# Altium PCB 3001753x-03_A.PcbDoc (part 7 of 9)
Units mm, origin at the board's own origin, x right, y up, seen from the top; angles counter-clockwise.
Board outline 210 x 130 mm, 8 copper layers (1-TOP, 2-GND, 3-INTOP, 4-PWR, 5-PWR, 6-INBOT, 7-GND, 8-BOTTOM), stack 1.646 mm thick; 676 components, 623 nets, 2861 pads, 2382 vias.
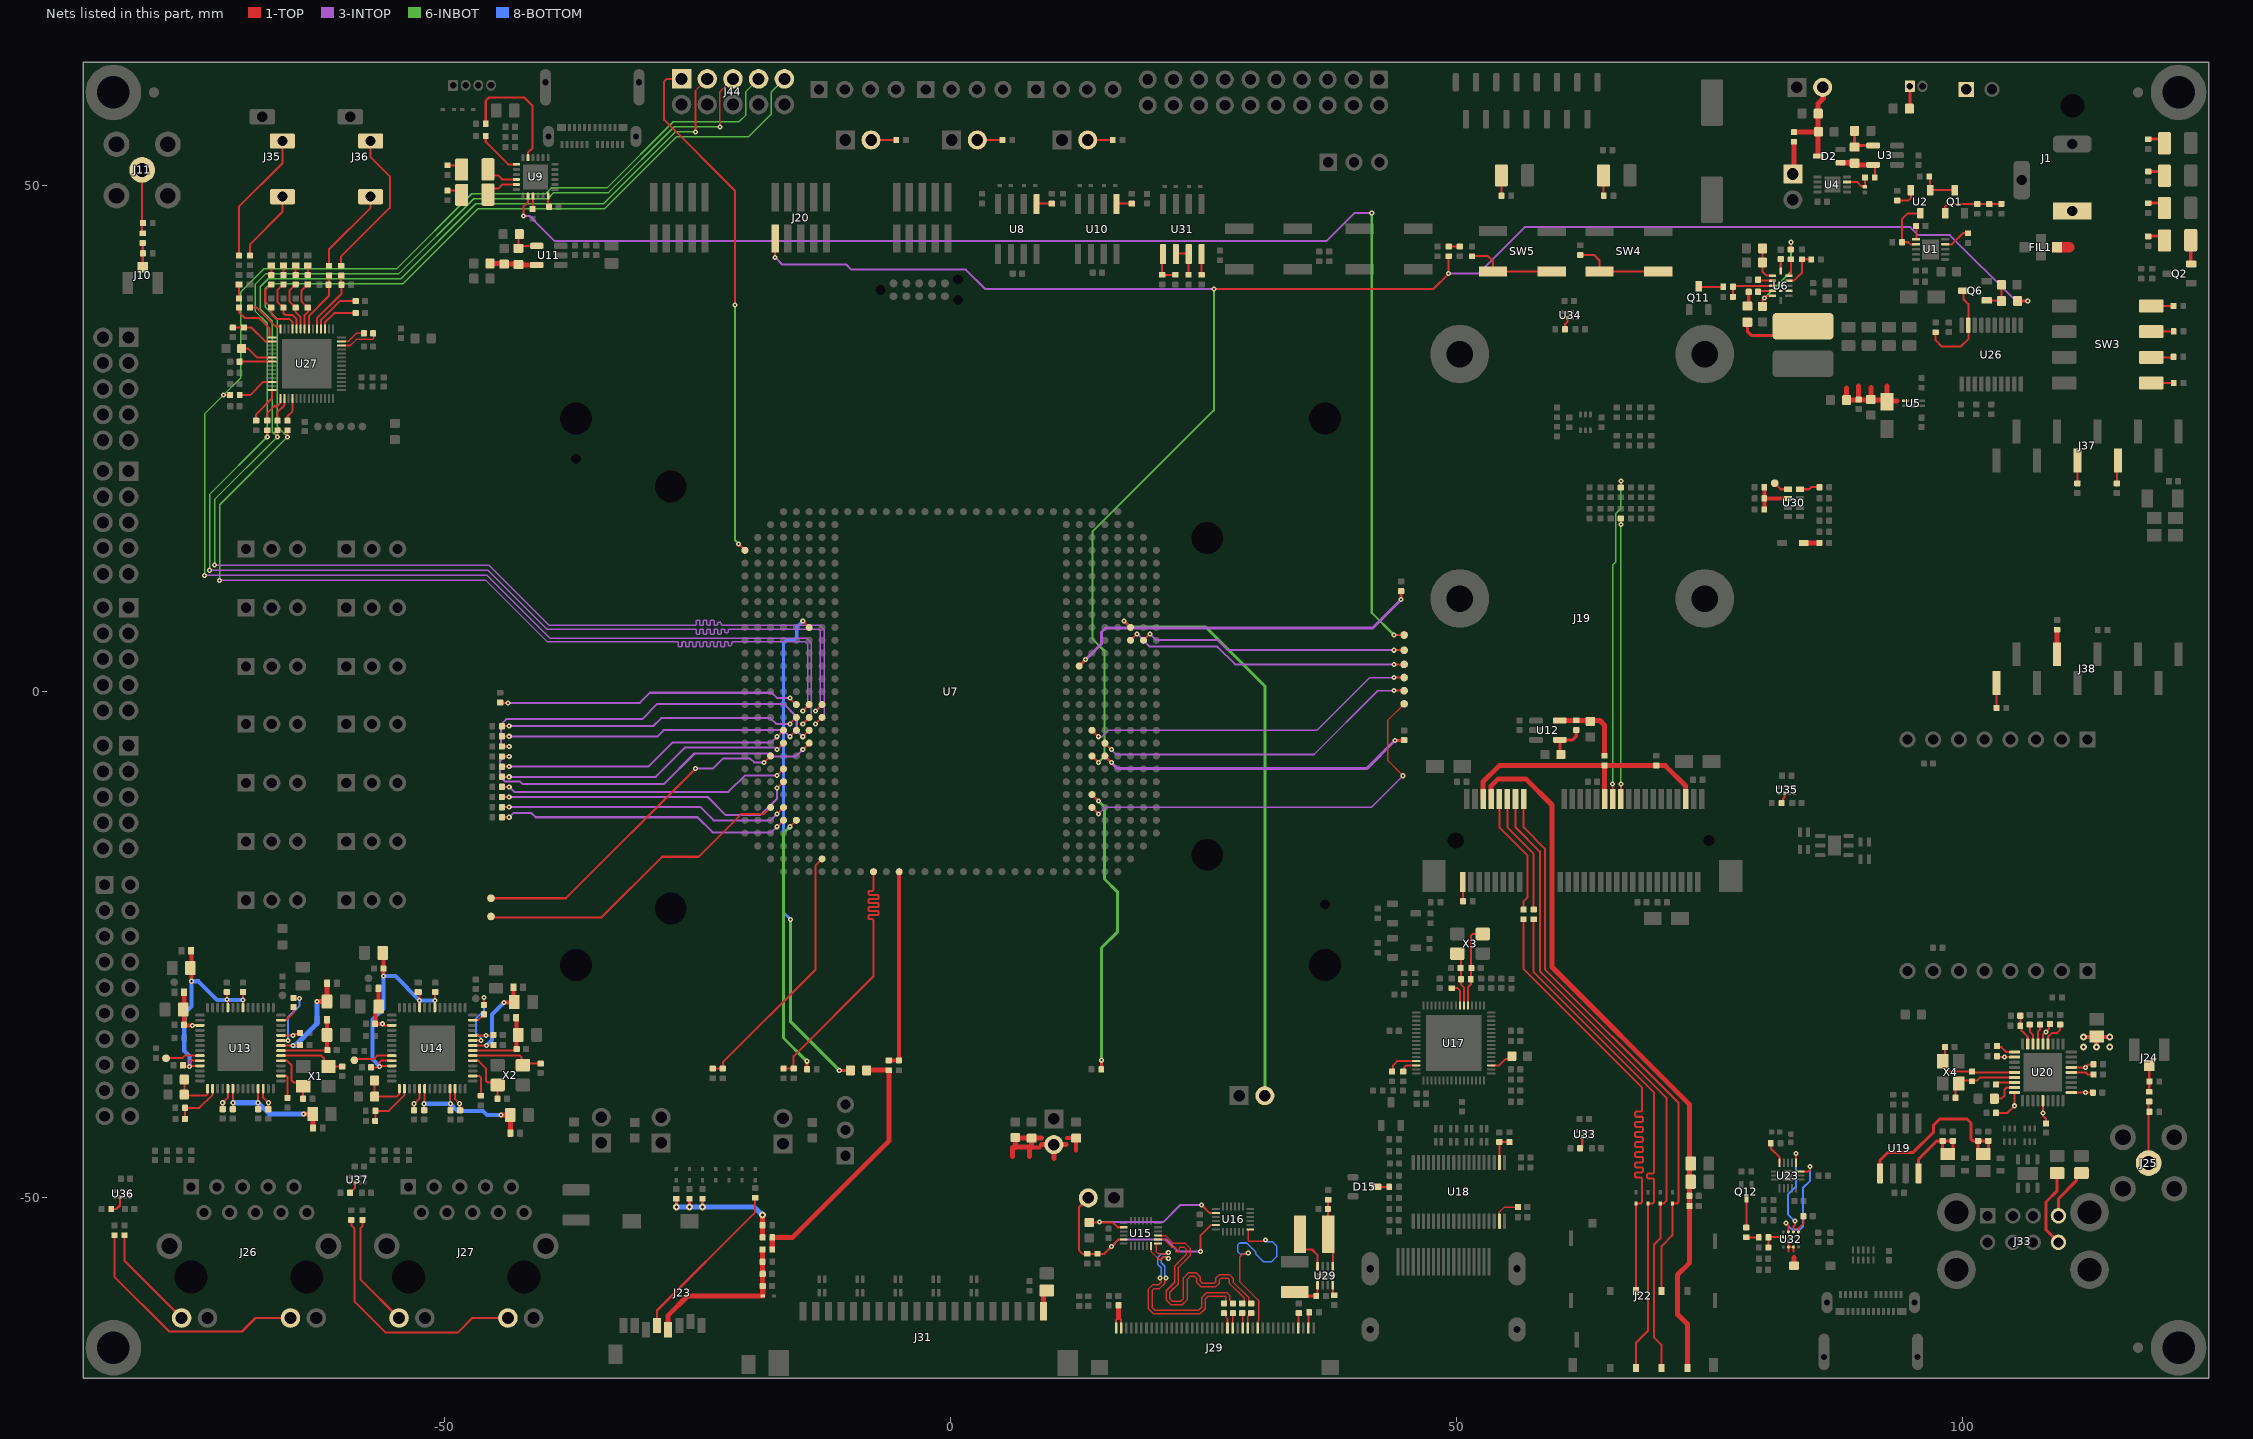
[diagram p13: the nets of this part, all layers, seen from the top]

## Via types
v1: diameter 0.5, hole 0.2, 1-TOP to 8-BOTTOM, 1547 vias
v2: diameter 0.68, hole 0.3, 1-TOP to 8-BOTTOM, 835 vias

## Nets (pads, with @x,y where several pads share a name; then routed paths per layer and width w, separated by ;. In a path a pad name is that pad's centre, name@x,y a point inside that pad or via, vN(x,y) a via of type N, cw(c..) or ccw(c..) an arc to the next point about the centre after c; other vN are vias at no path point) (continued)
MIPI_EXT_DATA1_P: J29.29 U16.19 | length 21
  1-TOP w0.15: v1(29.4,-55.423) 29.4,-55.446 29.3,-55.546 28.854,-55.546 28.546,-55.854 28.546,-58.246 30.423,-60.123 30.423,-61.823 30.423,-62.09 30.35,-62.163 J29.29@30.35,-62.85 ; U16.19@29.4,-53.1 29.4,-54.2 29.5,-54.3 30.977,-54.3 v1(31.1,-54.177)
  8-BOTTOM w0.15: v1(29.4,-55.423) 29.277,-55.546 28.596,-55.546 28.354,-55.304 28.354,-54.647 28.547,-54.454 29.254,-54.454 30.146,-55.346 30.146,-55.546 30.9,-56.3 31.7,-56.3 32.204,-55.796 32.204,-54.729 31.809,-54.334 31.257,-54.334 v1(31.1,-54.177)
MIPI_EXT_DATA2_N: R220.2 U15.21 | length 22.7
  1-TOP w0.15: U15.21@20.495,-53.7 20.518,-53.723 21.224,-53.723 22.001,-54.5 23.2,-54.5 23.65,-54.95 23.65,-55.719 22.5,-56.869 22.5,-58.476 21.654,-59.322 21.654,-59.929 21.925,-60.2 22.725,-60.2 23,-59.925 23,-57.9 23.5,-57.4 24.25,-57.4 24.679,-57.829 24.679,-58.228 24.897,-58.446 26.028,-58.446 26.2,-58.274 26.2,-57.925 26.55,-57.575 27.543,-57.575 27.897,-57.929 27.897,-58.296 29.464,-59.863 29.464,-60.384 R220.2@29.5,-60.42
MIPI_EXT_DATA2_P: R221.2 U15.20 | length 22.6
  1-TOP w0.15: U15.20@20.495,-54.1 20.518,-54.077 21.077,-54.077 21.854,-54.854 22.146,-54.854 22.234,-54.942 22.234,-55.281 22.286,-55.333 22.531,-55.333 22.584,-55.281 22.584,-54.942 22.672,-54.854 23.053,-54.854 23.296,-55.097 23.296,-55.572 22.146,-56.722 22.146,-58.329 21.3,-59.175 21.3,-60.076 21.778,-60.554 22.872,-60.554 23.354,-60.072 23.354,-58.047 23.647,-57.754 24.103,-57.754 24.325,-57.976 24.325,-58.375 24.75,-58.8 26.175,-58.8 26.554,-58.421 26.554,-58.071 26.696,-57.929 27.396,-57.929 27.543,-58.075 27.543,-58.443 29,-59.9 R221.2@29,-60.2
MIPI_EXT_DATA3_N: R222.2 U15.18 | length 19.7
  1-TOP w0.15: U15.18@19.8,-54.745 19.8,-55.3 20.35,-55.85 20.449,-55.85 20.537,-55.938 20.537,-56.051 20.59,-56.103 20.835,-56.103 20.887,-56.051 20.887,-55.938 20.975,-55.85 21.373,-55.85 v1(21.5,-55.977) ; v1(21.277,-57.9) 21.154,-58.023 21.154,-58.447 20.647,-58.954 20.097,-58.954 19.9,-59.151 19.9,-59.649 19.9,-60.175 19.9,-60.799 20.201,-61.1 24.499,-61.1 24.8,-60.799 24.8,-59.85 25.304,-59.346 27.27,-59.346 27.554,-59.63 27.554,-60.074 R222.2@27.9,-60.42
  8-BOTTOM w0.15: v1(21.277,-57.9) 21.154,-57.777 21.154,-56.753 20.8,-56.399 20.8,-56.054 21,-55.854 21.377,-55.854 v1(21.5,-55.977)
MIPI_EXT_DATA3_P: R223.2 U15.19 | length 19.4
  1-TOP w0.15: U15.19@20.3,-54.5 20.3,-55.3 20.5,-55.5 21.377,-55.5 v1(21.5,-55.377) ; v1(20.677,-57.9) 20.8,-58.023 20.8,-58.3 20.5,-58.6 19.95,-58.6 19.546,-59.004 19.546,-60.946 20.054,-61.454 24.646,-61.454 25.154,-60.946 25.154,-59.997 25.451,-59.7 27.123,-59.7 27.2,-59.777 27.2,-60.32 R223.2@27.1,-60.42
  8-BOTTOM w0.15: v1(20.677,-57.9) 20.8,-57.777 20.8,-56.9 20.446,-56.546 20.446,-55.907 20.853,-55.5 21.377,-55.5 v1(21.5,-55.377)
MIPI_SWITCH_OE: R116.2 U15.8 U16.8 | length 16.1
  1-TOP w0.2: R116.2@13.7,-52.43 16.03,-52.43 16.5,-52.9 U15.8@17.105,-52.9 ; v1(24.8,-50.7) 25.6,-51.5 U16.8@26.205,-51.5
  3-INTOP w0.2: v1(14.7,-52.4) 21,-52.4 22.7,-50.7 v1(24.8,-50.7)
MIPI_SWITCH_SEL: J28.2 R115.2 R117.1 U15.11 U16.11 | length 23.8
  1-TOP w0.2: J28.2@13.6,-50 12.7,-50.9 12.7,-55.2 13.02,-55.52 R117.1@13.5,-55.52 R115.2@14.5,-55.52 15.18,-55.52 v1(15.9,-54.8) 16.6,-54.1 U15.11@17.105,-54.1 ; v1(24.7,-55.3) 24.7,-53.7 25.7,-52.7 U16.11@26.205,-52.7
  3-INTOP w0.2: v1(15.9,-54.8) 16.6,-54.1 21.3,-54.1 22.5,-55.3 v1(24.7,-55.3)
MUX_3V3_1V8: R38.1 R39.1 R84.2 R85.2 | length 25.8
  1-TOP w0.5: R85.2@-17.62,-55.1 R84.2@-17.62,-53.9 -15.6,-53.9 -6.1,-44.4 R39.1@-6.1,-37.4 ; R38.1@-8.28,-37.38 R39.1@-6.1,-37.38
NetC5_2: C5.2 U1.6 | length 1.3
  1-TOP w0.2: U1.6@95.4,44.7 95.4,45.76 C5.2@95.54,45.9
NetC6_1: C6.1 Q1.G R13.2 R14.1 | length 6.3
  1-TOP w0.2: Q1.G@98.25,47.25 98.25,47.95 98.48,48.18 R14.1@101.4,48.18 R13.2@103.8,48.18
NetC7_2: C7.2 D2.3 J3.2 R16.1 R18.2 | length 8.9
  1-TOP w0.5: R18.2@83.3,55.28 C7.2@85.71,55.28 ; D2.3@85.7,52.9 C7.2@85.7,55.27 ; R16.1@85.7,56.6 85.7,55.33 C7.2@85.73,55.3 ; R16.1@85.7,57.1 85.7,58.1 86.2,58.6 86.2,59.64 J3.2@86.14,59.7
NetC11_1: C11.1 U6.10 | length 1.4
  1-TOP w0.2: C11.1@79.76,39.6 U6.10@81.2,39.6
NetC11_2: C11.2 R23.1 | length 1.6
  1-TOP w0.3: R23.1@78.7,38.1 78.84,38.24 C11.2@78.84,39.6
NetC16_1: C16.1 C21.2 C22.2 R24.1 U5.1 | length 9.9
  1-TOP w0.2: C16.1@92.35,28.8 C16.1@92.5,28.65
  1-TOP w0.5: 88.5,30 R24.1@88.5,28.8 89.7,28.8 90.9,28.8 C16.1@92.35,28.8 ; C22.2@89.7,29 89.7,30.2 ; C21.2@90.9,28.87 90.9,30.07 ; C16.1@92.425,28.725 93.5,28.725 ; C16.1@92.5,29 92.5,30.2
NetC23_1: C23.1 U6.8 | length 1.5
  1-TOP w0.2: C23.1@79.76,40.7 79.86,40.6 U6.8@81.2,40.6
NetC24_2: C24.2 R30.1 U6.11 | length 9.1
  1-TOP w0.2: C24.2@80.2,38.07 80.2,38.7 v1(80.4,38.9) 80.6,39.1 U6.11@81.2,39.1 ; R30.1@83,43.68 v1(83,44.4)
  6-INBOT w0.2: v1(80.4,38.9) 83,41.5 v1(83,44.4)
NetC25_2: C25.2 U6.6 | length 1.2
  1-TOP w0.2: U6.6@82,41.55 C25.2@82,42.74
NetC31_1: C31.1 U9.12 | length 1.1
  1-TOP w0.2: U9.12@-39.75,48.95 -39.75,47.99 C31.1@-39.66,47.9
NetC33_2: C33.2 R74.1 R76.2 U11.5 | length 4.7
  1-TOP w0.2: C33.2@-44.17,42.3 C33.2@-44.1,42.23 ; R76.2@-42.73,42.23 R76.2@-42.7,42.2
  1-TOP w0.5: R74.1@-45.5,42.3 C33.2@-44.17,42.3 ; C33.2@-44.1,42.23 R76.2@-42.73,42.23 ; R76.2@-42.7,42.15 U11.5@-40.88,42.15
NetC38_2: C38.2 R81.1 R82.2 U12.5 | length 7.6
  1-TOP w0.5: U12.5@60.18,-2.85 61.8,-2.85 63.2,-2.85 64.15,-2.85 64.6,-3.3 R81.1@64.6,-6.32
NetC48_2: C48.2 C49.2 D1.1 J23.4 R85.1 R88.1 | length 16.2
  1-TOP w0.5: J23.4@-27.9,-63.025 -27.9,-61.6 -26,-59.7 -18.56,-59.7 C48.2@-18.56,-58.7 ; C48.2@-18.58,-58.7 -18.58,-57.5 R88.1@-18.58,-56.3 R85.1@-18.58,-55.1
NetC58_2: C58.2 C59.2 L2.1 U13.36 | length 10.3
  1-TOP w0.2: U13.36@-66.15,-34.95 v1(-64.95,-34.95) C58.2@-64.41,-34.95 ; C58.2@-64.5,-34.95 C58.2@-64.41,-34.95 ; C58.2@-64.5,-34.9 -64.36,-34.9 C58.2@-64.41,-34.95
  1-TOP w0.5: v1(-62.6,-30.6) C59.2@-61.6,-30.6 -61.58,-30.58 L2.1@-61.58,-28.8
  8-BOTTOM w0.5: v1(-64.95,-34.95) -64.75,-34.95 -62.6,-32.8 v1(-62.6,-30.6)
NetC60_2: C60.2 C61.2 C62.2 L3.1 U13.20 U13.25 | length 14
  1-TOP w0.2: C61.2@-70.9,-41.34 v1(-70.9,-40.6) U13.20@-70.9,-39.2 ; C60.2@-68.4,-41.34 v1(-68.4,-40.6) U13.25@-68.4,-39.2
  1-TOP w0.5: v1(-63.9,-41.7) C62.2@-63,-41.7 -62.98,-41.72 L3.1@-62.98,-43.1
  8-BOTTOM w0.5: v1(-70.9,-40.6) v1(-68.4,-40.6) -67.3,-41.7 v1(-63.9,-41.7)
NetC63_2: C63.2 C64.2 C65.2 C66.2 L4.1 U13.10 U13.11 U13.49 U13.52 | length 24.3
  1-TOP w0.2: C63.2@-75.84,-36.9 C63.2@-75.74,-36.8 ; C63.2@-75.8,-37 v1(-75.2,-37) ; L4.1@-75.02,-25.6 L4.1@-75,-25.62 ; U13.11@-74.15,-36.95 -75.15,-36.95 v1(-75.2,-37) ; U13.10@-74.15,-36.45 -75.05,-36.45 -75.2,-36.6 v1(-75.2,-37) ; C65.2@-71.5,-29.66 v1(-71.5,-30.4) -71.4,-30.4 U13.52@-71.4,-31.2 ; U13.49@-69.9,-31.2 v1(-69.9,-30.43) C64.2@-69.9,-29.66
  1-TOP w0.4: v1(-75,-28.6) L4.1@-75,-25.62
  8-BOTTOM w0.4: v1(-75.2,-37) -75.2,-36 -75.7,-35.5 -75.7,-31.8 -75,-31.1 v1(-75,-28.6) -74.3,-28.6 -72.47,-30.43 -71.53,-30.43 v1(-71.5,-30.4) -71.47,-30.43 v1(-69.9,-30.43)
NetC67_1: C67.1 R103.1 U13.16 | length 4.9
  1-TOP w0.2: C67.1@-75.64,-42.2 -75.64,-41.12 R103.1@-75.62,-41.1 ; R103.1@-75.6,-41.1 -74.2,-41.1 -72.9,-39.8 U13.16@-72.9,-39.2
NetC68_2: C68.2 U13.34 X1.1 | length 6.3
  1-TOP w0.2: U13.34@-66.15,-35.95 -62.15,-35.95 -61.9,-36.2 X1.1@-61.9,-36.8 ; X1.1@-61.45,-37.025 -61.435,-37.04 C68.2@-60.1,-37.04
NetC69_2: C69.2 C70.2 L5.1 U13.35 | length 7.1
  1-TOP w0.2: U13.35@-66.15,-35.45 C69.2@-61.76,-35.45 ; C69.2@-61.6,-35.36 C69.2@-61.56,-35.4
  1-TOP w0.4: C69.2@-61.6,-35.36 C70.2@-61.6,-33.9 ; C70.2@-61.58,-33.9 L5.1@-61.58,-32.72
NetC71_2: C71.2 U13.33 X1.3 | length 4.6
  1-TOP w0.2: U13.33@-66.15,-36.45 -65.55,-36.45 -65.1,-36.9 -65.1,-38.4 -64.9,-38.6 X1.3@-64.5,-38.6 ; C71.2@-63.96,-40.2 -63.96,-38.985 X1.3@-63.95,-38.975
NetC72_2: C72.2 C73.2 C74.2 C75.2 C76.2 L6.1 U13.3 U13.19 U13.26 U13.38 | length 11.2
  1-TOP w0.2: v1(-74.9,-32.95) U13.3@-74.15,-32.95 ; C73.2@-71.9,-41.34 v1(-71.9,-40.6) -71.4,-40.1 U13.19@-71.4,-39.2 ; U13.26@-67.9,-39.2 -67.9,-40.1 v1(-67.4,-40.6) C74.2@-67.4,-41.34 ; U13.38@-66.15,-33.95 v1(-64.95,-33.95) -64.8,-33.8 C75.2@-64.5,-33.8
  1-TOP w0.4: L6.1@-75.82,-29.7 -75.7,-29.82 -75.7,-32.9 -75.65,-32.95 v1(-74.9,-32.95)
NetC80_1: C80.1 U13.37 | length 6
  1-TOP w0.2: U13.37@-66.15,-34.45 v1(-65.45,-34.45) ; C80.1@-64.9,-30.24 -64.84,-30.3 v1(-64.3,-30.3)
  8-BOTTOM w0.2: v1(-65.45,-34.45) -65.45,-32.15 -64.3,-31 v1(-64.3,-30.3)
NetC80_2: C80.2 U13.41 | length 2.1
  1-TOP w0.2: U13.41@-66.15,-32.45 -65.65,-32.45 -64.9,-31.7 C80.2@-64.9,-31.16
NetC85_2: C85.2 C86.2 L7.1 U14.36 | length 9.4
  1-TOP w0.2: U14.36@-47.2,-34.95 v1(-45.85,-34.95) -45.21,-34.95 C85.2@-45.16,-34.9
  1-TOP w0.4: v1(-44.1,-30.7) C86.2@-43.145,-30.7 ; L7.1@-43.2,-29.27 -43.2,-30.54 C86.2@-43.09,-30.65
  8-BOTTOM w0.4: v1(-45.85,-34.95) -45.3,-34.4 -45.3,-31.9 v1(-44.1,-30.7)
NetC87_2: C87.2 C88.2 C89.2 L8.1 U14.20 U14.25 | length 15.2
  1-TOP w0.2: C88.2@-51.95,-41.29 C88.2@-52,-41.34 v1(-52,-40.7) -51.95,-40.65 U14.20@-51.95,-39.2 ; U14.25@-49.45,-39.2 -49.45,-40.65 v1(-49.4,-40.7) C87.2@-49.4,-41.34
  1-TOP w0.4: C89.2@-43.5,-41.8 C89.2@-43.48,-41.82
  1-TOP w0.5: v1(-44.4,-41.8) C89.2@-43.5,-41.8 ; L8.1@-43.48,-43.6 C89.2@-43.48,-41.82
  8-BOTTOM w0.4: v1(-52,-40.7) v1(-49.4,-40.7) -48.7,-41.4 -46.2,-41.4 -45.8,-41.8 v1(-44.4,-41.8)
NetC90_2: C90.2 C91.2 C92.2 C93.2 L9.1 U14.10 U14.11 U14.49 U14.52 | length 25
  1-TOP w0.2: C90.2@-57.24,-37.1 -56.4,-37.1 v1(-56.4,-37) ; C93.2@-56.1,-25.8 C93.2@-56.03,-25.87 ; U14.11@-55.2,-36.95 -56.35,-36.95 v1(-56.4,-37) ; U14.10@-55.2,-36.45 -56.25,-36.45 -56.4,-36.6 v1(-56.4,-37) ; L9.1@-52.6,-29.68 -52.45,-29.83 v1(-52.45,-30.5) U14.52@-52.45,-31.2 ; U14.49@-50.95,-31.2 v1(-50.95,-30.5) -50.95,-29.71 C92.2@-50.9,-29.66
  1-TOP w0.4: v1(-56.03,-28.1) C91.2@-56.03,-27.35 C93.2@-56.03,-25.87
  8-BOTTOM w0.4: v1(-56.4,-37) -57.1,-36.3 -57.1,-32.4 -56.03,-31.33 v1(-56.03,-28.1) -54.85,-28.1 v1(-52.45,-30.5) v1(-50.95,-30.5)
NetC94_1: C94.1 R112.1 U14.16 | length 5.2
  1-TOP w0.2: C94.1@-56.82,-42.5 C94.1@-56.82,-42.4 ; C94.1@-56.82,-42.32 R112.1@-56.82,-41.4 -55.5,-41.4 -53.95,-39.85 U14.16@-53.95,-39.2
NetC95_2: C95.2 U14.34 X2.1 | length 7.2
  1-TOP w0.2: U14.34@-47.2,-35.95 -42.55,-35.95 -42.4,-36.1 X2.1@-42.4,-36.6 ; X2.1@-42.25,-36.9 -42.09,-36.74 C95.2@-40.5,-36.74
NetC96_2: C96.2 C97.2 L10.1 U14.35 | length 7.8
  1-TOP w0.2: U14.35@-47.2,-35.45 C96.2@-42.9,-35.45 ; C97.2@-43,-33.6 -42.86,-33.74 C97.2@-42.7,-33.9
  1-TOP w0.4: C96.2@-42.86,-35.3 -42.86,-34.26 -42.86,-33.74 L10.1@-42.86,-32.2
NetC98_2: C98.2 U14.33 X2.3 | length 5.2
  1-TOP w0.2: U14.33@-47.2,-36.45 -46.65,-36.45 -45.9,-37.2 -45.9,-38.4 -45.7,-38.6 X2.3@-45.2,-38.6 ; X2.3@-44.9,-38.4 X2.3@-44.75,-38.55 ; C98.2@-44.76,-40.2 -44.76,-38.86 X2.3@-44.75,-38.85
NetC99_2: C99.2 C100.2 C101.2 C102.2 C103.2 L11.1 U14.3 U14.19 U14.26 U14.38 | length 12.1
  1-TOP w0.2: C103.2@-56.64,-31.24 C103.2@-56.5,-31.1 C103.2@-56.52,-31.08 ; v1(-56.1,-32.8) -55.95,-32.95 U14.3@-55.2,-32.95 ; C100.2@-53,-41.34 v1(-53,-40.7) -52.45,-40.15 U14.19@-52.45,-39.2 ; U14.26@-48.95,-39.2 -48.95,-40.25 v1(-48.5,-40.7) -48.5,-41.29 C101.2@-48.45,-41.34 ; U14.38@-47.2,-33.95 v1(-45.9,-33.95) -45.21,-33.95 C102.2@-45.16,-33.9
  1-TOP w0.4: C99.2@-56.84,-32.8 -56.8,-32.76 -56.8,-31.4 C103.2@-56.5,-31.1 ; C99.2@-56.64,-32.8 v1(-56.1,-32.8) ; C103.2@-56.52,-31.08 L11.1@-56.52,-29.3
NetC107_1: C107.1 U14.37 | length 6.4
  1-TOP w0.2: U14.37@-47.2,-34.45 v1(-46.4,-34.45) v1@-46.35,-34.45 ; C107.1@-46.1,-30.94 v1(-46.1,-30.2)
  8-BOTTOM w0.2: v1(-46.4,-34.45) -46.4,-34.2 -46.9,-33.7 -46.9,-32.3 -46.1,-31.5 v1(-46.1,-30.2)
NetC107_2: C107.2 U14.41 | length 1.3
  1-TOP w0.2: U14.41@-47.2,-32.45 -46.69,-32.45 C107.2@-46.1,-31.86
NetC113_2: C113.2 R119.1 U18.2 | length 3
  1-TOP w0.15: R119.1@55.18,-44.46 R119.1@55.2,-44.48
  1-TOP w0.2: U18.2@54.2,-46.5 C113.2@54.2,-44.46 R119.1@55.18,-44.46
NetC114_2: C114.2 R123.2 U17.53 X3.1 | length 8.2
  1-TOP w0.2: U17.53@51.1,-30.995 51.1,-29.205 51.385,-28.92 R123.2@51.385,-28.4 51.385,-27.3 51.385,-24.12 51.58,-23.925 X3.1@52.555,-23.925
NetC116_2: C116.2 R123.1 U17.54 X3.3 | length 5.4
  1-TOP w0.2: X3.3@50.055,-25.875 50.425,-26.245 50.425,-27.3 R123.1@50.425,-28.4 50.425,-28.926 50.7,-29.201 U17.54@50.7,-30.995
NetC117_1: C117.1 U17.35 | length 2
  1-TOP w0.2: U17.35@53.405,-36.9 54.2,-36.9 54.8,-36.3 C117.1@55.205,-36.3
NetC118_2: C118.2 U18.37 | length 2.9
  1-TOP w0.15: U18.37@54.2,-52.3 54.2,-51.4 54.7,-50.9 C118.2@56.04,-50.9
NetC137_1: C137.1 R142.1 U20.32 X4.3 | length 9.2
  1-TOP w0.2: C137.1@98.24,-35.1 98.24,-36.5 98.24,-37.34 98.42,-37.52 R142.1@100.9,-37.52 100.98,-37.6 U20.32@105.1,-37.6
NetC138_1: C138.1 R142.2 U20.33 X4.1 | length 7
  1-TOP w0.2: C138.1@99.26,-40.1 99.26,-39.04 X4.1@99.6,-38.7 ; X4.1@99.8,-38.38 100.9,-38.38 101.42,-38.38 101.7,-38.1 U20.33@105.1,-38.1
NetC140_2: C140.2 C143.2 L23.2 U19.8 | length 8.9
  1-TOP w0.3: U19.8@95.615,-47.57 95.615,-46.185 97.44,-44.36 C143.2@98,-44.36 ; C143.2@98,-44.36 C140.2@99,-44.36 99,-45.35 98.5,-45.85 98,-45.35 C143.2@98,-44.36
NetC141_2: C141.2 C142.2 L22.2 U19.5 | length 18.4
  1-TOP w0.3: U19.5@91.805,-47.57 91.805,-46.295 92.6,-45.5 95.1,-45.5 97.1,-43.5 97.1,-42.8 97.7,-42.2 100.4,-42.2 100.8,-42.6 100.8,-44.2 100.96,-44.36 C142.2@101.5,-44.36 101.5,-45.35 L22.2@102,-45.85 ; C142.2@101.66,-44.36 102.1,-44.36 C141.2@102.5,-44.36 L22.2@102.5,-45.307
NetC144_2: C144.2 R143.1 U20.26 | length 2.9
  1-TOP w0.2: R143.1@105.66,-33 C144.2@105.66,-32 ; R143.1@105.8,-33.1 105.8,-33.5 106.4,-34.1 U20.26@106.4,-34.8
NetC148_2: C148.2 C149.2 C150.2 C151.2 C152.2 C153.2 L28.1 U20.5 U20.10 U20.15 U20.23 U20.29 U20.36 | length 17.6
  1-TOP w0.2: C148.2@103.26,-41.6 104.4,-41.6 v1(105.1,-40.9) U20.36@105.1,-39.6 ; C153.2@103.36,-36 103.46,-36.1 v1(104.1,-36.1) U20.29@105.1,-36.1 ; U20.5@107.9,-40.4 v1(107.9,-41.6) 107.9,-41.9 108.2,-42.2 C149.2@108.2,-42.64 ; U20.23@107.9,-34.8 107.9,-33.9 v1(108.2,-33.6) 108.5,-33.3 C152.2@108.5,-33 ; U20.10@110.7,-39.6 v1(112.1,-39.6) C150.2@112.84,-39.6 ; U20.15@110.7,-37.1 v1(112.1,-37.1) 112.4,-36.8 C151.2@112.9,-36.8
  1-TOP w0.4: v2(111.9,-34.1) L28.1@113.15,-34.1 ; v2(113.2,-35.1) L28.1@113.2,-34.05 ; L28.1@113.25,-34.1 v2(114.5,-34.1)
  other v2: 111.9,-35.1 114.5,-35.1
NetC154_2: C154.2 U20.14 | length 2.3
  1-TOP w0.2: U20.14@110.7,-37.6 112.1,-37.6 112.3,-37.8 C154.2@112.9,-37.8
NetC155_2: C155.2 U20.34 | length 1.9
  1-TOP w0.2: C155.2@103.26,-38.8 103.46,-38.6 U20.34@105.1,-38.6
NetC156_2: C156.2 Q6.G R152.2 | length 3.1
  1-TOP w0.2: Q6.G@102.35,38.65 103.75,38.65 R152.2@103.8,38.6 C156.2@103.8,40.2
NetC158_1: C158.1 R165.2 U27.44 | length 4.4
  1-TOP w0.2: C158.1@-70.9,35.96 -70.88,35.98 R165.2@-69.8,35.98 -69.08,35.98 -67.7,34.6 U27.44@-67.03,34.6
NetC159_1: C159.1 U27.42 | length 3.8
  1-TOP w0.2: C159.1@-69.2,37.94 -68.54,37.94 -66.7,36.1 U27.42@-66.2,36.1
NetC160_1: C160.1 U27.43 | length 5
  1-TOP w0.2: C160.1@-70.3,37.94 -70.3,37.5 -69.7,36.9 -68.3,36.9 -67.3,35.9 U27.43@-67.3,35
NetC160_2: C160.2 L33.2 | length 1.4
  1-TOP w0.2: C160.2@-70.3,38.86 -70.27,38.89 L33.2@-70.27,40.228
NetC161_1: C161.1 C162.1 U27.39 | length 6.5
  1-TOP w0.2: C162.1@-67.1,40.24 -67.7,39.64 -67.7,38.54 C161.1@-67.1,37.94 -67.1,37.3 -66.6,36.8 -65.3,36.8 -65,36.5 U27.39@-65,35.83
NetC162_2: C162.2 L34.2 | length 1
  1-TOP w0.2: C162.2@-67.1,41.16 L34.2@-67.1,42.12
NetC163_1: C163.1 C165.1 U27.38 | length 5.9
  1-TOP w0.2: C163.1@-65.9,40.24 -66.5,39.64 -66.5,38.54 C165.1@-65.9,37.94 -65.9,37.4 -65.7,37.2 -65,37.2 -64.6,36.8 U27.38@-64.6,35.83
NetC163_2: C163.2 L35.2 | length 1
  1-TOP w0.2: C163.2@-65.9,41.16 L35.2@-65.9,42.12
NetC164_1: C164.1 R168.1 U27.35 | length 6.1
  1-TOP w0.2: U27.35@-63.4,35.83 -63.4,37.1 -61.4,39.1 -61.4,40.2 R168.1@-61.4,41.12
NetC166_1: C166.1 C167.1 U27.37 | length 5.1
  1-TOP w0.2: C167.1@-64.7,40.24 -65.3,39.64 -65.3,38.54 C166.1@-64.7,37.94 -64.7,37.5 -64.2,37 U27.37@-64.2,35.83
NetC167_2: C167.2 L36.2 | length 1
  1-TOP w0.2: C167.2@-64.7,41.16 L36.2@-64.7,42.12
NetC168_1: C168.1 R169.1 U27.33 | length 6.3
  1-TOP w0.2: U27.33@-62.6,35.83 -62.6,36.9 -60.16,39.34 C168.1@-60.16,40.2 -60.2,40.24 R169.1@-60.2,41.12
NetC169_1: C169.1 C170.1 U27.36 | length 5
  1-TOP w0.2: U27.36@-63.8,35.83 -63.8,37.2 -63.5,37.5 C170.1@-63.5,37.94 -64.1,38.54 -64.1,39.64 C169.1@-63.5,40.24
NetC169_2: C169.2 L37.2 | length 1
  1-TOP w0.2: C169.2@-63.5,41.16 L37.2@-63.5,42.12
NetC172_1: C172.1 U27.27 | length 2.5
  1-TOP w0.15: U27.27@-60.17,34.6 -59.5,34.6 -58.7,35.4 C172.1@-57.96,35.4
NetC172_2: C172.2 U27.26 | length 4.1
  1-TOP w0.15: U27.26@-60.17,34.2 -59.3,34.2 -58.7,34.8 -57.1,34.8 -57,34.9 C172.2@-57,35.509
NetC174_2: C174.2 U27.32 | length 5.1
  1-TOP w0.2: U27.32@-62.2,35.83 -62.2,36.7 -60.3,38.6 C174.2@-58.796,38.6
NetC179_2: C179.2 U27.31 | length 4.2
  1-TOP w0.2: U27.31@-61.8,35.83 -61.8,36.5 -60.9,37.4 C179.2@-58.691,37.4
NetC180_2: C180.2 U27.48 | length 3.4
  1-TOP w0.2: C180.2@-70.03,33.9 -69.4,33.9 -68.5,33 U27.48@-67.03,33
NetC181_2: C181.2 U27.49 | length 2.9
  1-TOP w0.2: -69.94,32.6 U27.49@-67.03,32.6
NetC189_2: C189.2 L42.1 R216.2 U29.1 | length 6.9
  1-TOP w0.2: L42.1@37.3,-53.327 37.3,-51 R216.2@37.3,-50.107 ; L42.1@37.48,-53.42 L42.1@37.3,-53.6 L42.1@37.65,-53.95 ; U29.1@37.75,-56.765 L42.1@37.75,-53.85
NetC190_2: C190.2 R217.2 U29.5 | length 3.4
  1-TOP w0.2: C190.2@33.7,-59.4 C190.2@34,-59.7 ; R217.2@36.22,-59.7 36.25,-59.67 U29.5@36.25,-58.635
  1-TOP w0.3: C190.2@34,-59.7 R217.2@35.92,-59.7
NetC201_2: C201.2 U32.D4 | length 1.8
  1-TOP w0.2: U32.D4@83.75,-53.35 83.75,-53.05 84.24,-52.56 C201.2@84.24,-51.8
NetD2_1: D2.1 R19.2 R20.2 U3.5 | length 4.6
  1-TOP w0.2: U3.5@91.12,52.05 91.3,51.87 91.3,50.82 R20.2@91.28,50.8
  1-TOP w0.3: R19.2@89.25,52.25 R19.2@89.3,52.2 R19.2@89.45,52.05
  1-TOP w0.5: D2.1@87.9,52.25 R19.2@89.25,52.25 ; R19.2@89.45,52.05 U3.5@91.12,52.05
NetD5_A: D5.A R70.2 | length 1.6
  1-TOP w0.2: R70.2@-49.7,52 -48.725,52 D5.A@-48.3,51.575
NetD5_K: D5.K U9.4 | length 3.2
  1-TOP w0.2: D5.K@-45.7,51.6 -45.1,51 -44.7,51 -44.3,50.6 U9.4@-42.9,50.6
NetD6_A: D6.A R71.2 | length 1.6
  1-TOP w0.2: R71.2@-49.7,49.5 -48.725,49.5 D6.A@-48.3,49.075
NetD6_K: D6.K U9.5 | length 3.2
  1-TOP w0.2: D6.K@-45.7,49.1 -45.1,49.7 -44.7,49.7 -44.3,50.1 U9.5@-42.9,50.1
NetD13_2: D13.2 J22.3 R86.2 | length 51.5
  1-TOP w0.2: R86.2@57.6,-22.48 57.6,-27.7 69.5,-39.6 69.5,-45.485 69.5,-47.455 69.383,-47.572 68.91,-47.572 68.81,-47.672 68.81,-47.972 68.91,-48.072 69.383,-48.072 69.5,-48.189 69.5,-48.289 69.5,-50.4 69.35,-50.55 D13.2@68.9,-50.55 68.9,-63.1 67.7,-64.3 J22.3@67.7,-66.92
NetD14_2: D14.2 J22.7 R89.2 | length 51.3
  1-TOP w0.2: R89.2@56.6,-22.48 56.6,-27.4 68.3,-39.1 68.3,-39.978 68.3,-41.366 68.183,-41.483 67.716,-41.483 67.616,-41.583 67.616,-41.883 67.716,-41.983 68.288,-41.983 68.388,-42.083 68.388,-42.383 68.288,-42.483 67.707,-42.483 67.607,-42.583 67.607,-42.883 67.707,-42.983 68.288,-42.983 68.388,-43.083 68.388,-43.383 68.288,-43.483 67.707,-43.483 67.607,-43.583 67.607,-43.883 67.707,-43.983 68.288,-43.983 68.388,-44.083 68.388,-44.383 68.288,-44.483 67.707,-44.483 67.607,-44.583 67.607,-44.883 67.707,-44.983 68.288,-44.983 68.388,-45.083 68.388,-45.383 68.288,-45.483 67.707,-45.483 67.607,-45.583 67.607,-45.883 67.707,-45.983 68.288,-45.983 68.388,-46.083 68.388,-46.383 68.288,-46.483 67.707,-46.483 67.607,-46.583 67.607,-46.883 67.707,-46.983 68.288,-46.983 68.388,-47.083 68.388,-47.383 68.288,-47.483 67.707,-47.483 67.607,-47.583 67.607,-47.883 67.707,-47.983 68.183,-47.983 68.3,-48.1 68.3,-48.2 68.3,-50.4 68.15,-50.55 D14.2@67.7,-50.55 J22.7@67.7,-59.3
NetD15_K: D15.K R120.1 | length 1.3
  1-TOP w0.2: D15.K@42.05,-48.9 R120.1@43.32,-48.9
NetD17_A: D17.A R206.1 | length 4
  1-TOP w0.2: D17.A@64.498,51.025 64.498,49.022 64.5,49.02 D17.A@64.5,51
NetD18_A: D18.A R207.1 | length 1.7
  1-TOP w0.2: R207.1@54.42,49 D18.A@54.42,50.68
NetD21_A: D21.A U32.B1 U32.B2 U32.C1 | length 2.7
  1-TOP w0.2: 82.75,-55.308 U32.B1@82.75,-54.85 ; U32.B2@82.75,-54.35 U32.B1@82.75,-54.85 ; 83.25,-55.308 U32.C1@83.25,-54.85 U32.B1@82.75,-54.85
  1-TOP w0.5: D21.A@83.3,-56.7 83.3,-55.9
NetD31_A: D31.A R12.1 | length 1.7
  1-TOP w0.3: R12.1@118.3,44.98 118.28,45 D31.A@120,45
NetD31_K: D31.K Q2.S | length 2.4
  1-TOP w0.3: D31.K@122.5,44.6 122.5,42.3 Q2.S@122.55,42.25
NetD32_A: D32.A R15.1 | length 1.8
  1-TOP w0.3: R15.1@118.3,48.26 119.415,48.26 D32.A@119.9,47.775
NetD33_A: D33.A R154.1 | length 1.8
  1-TOP w0.3: R154.1@118.3,51.38 119.495,51.38 D33.A@119.9,50.975
NetD34_A: D34.A R195.1 | length 1.8
  1-TOP w0.3: R195.1@118.3,54.58 119.495,54.58 D34.A@119.9,54.175
NetD35_K: D35.K R242.2 | length 1.5
  1-TOP w0.5: D35.K@84.27,14.7 R242.2@85.82,14.7
NetFIL1_1: FIL1.1 J1.1 J2.1 | length 1.2
  1-TOP w1: FIL1.1@109.3,43.9 110.5,43.9
NetJ4_1: J4.1 R17.1 | length 2.2
  1-TOP w0.3: R17.1@94.75,57.6 J4.1@94.75,59.8
NetJ5_1: J5.1 R18.1 | length 3.2
  1-TOP w0.3: J5.1@83.2,51.14 J5.1@83.3,51.24
  1-TOP w0.5: J5.1@83.3,51.24 R18.1@83.3,54.32
NetJ6_2: J6.2 R33.2 R34.1 R35.1 | length 13.9
  1-TOP w0.4: 7.8,-45 8,-45 8.8,-45 ; 11.5,-44.1 R33.2@12.4,-44.1 12.4,-45.3
  1-TOP w0.5: 6.1,-45.93 6.1,-45 ; 6.4,-45 6.4,-44.97 ; 7.8,-45.9 7.8,-45 7.8,-44.97 6.4,-44.97 ; 8,-45.03 8,-45 R34.1@8,-44.1 8.963,-44.1 ; R34.1@8,-44.07 6.4,-44.07 6.4,-44.97 ; 8.993,-44.736 J6.2@10.2,-44.736 11.407,-44.736 ; 10.2,-46.1 J6.2@10.2,-45.443
NetJ9_2: J9.2 U7.AL20 | length 57.9
  1-TOP w0.2: v1(17.145,6.985) U7.AL20@17.78,6.35
  6-INBOT w0.3: v1(17.145,6.985) 17.73,6.4 25.2,6.4 31.04,0.56 J9.2@31.04,-39.9
NetJ10_1: J10.1 R58.2 R59.2 | length 2.4
  1-TOP w0.2: J10.1@-79.8,41.925 -79.8,43.3 R58.2@-79.8,44.32
NetJ11_1: J11.1 R58.1 R60.2 | length 6.3
  1-TOP w0.2: J11.1@-79.86,51.54 -79.86,45.34 R58.1@-79.8,45.28
NetJ14_2: J14.2 R66.2 | length 2.5
  1-TOP w0.2: J14.2@-7.86,54.5 R66.2@-5.38,54.5
NetJ16_2: J16.2 R77.2 | length 2.5
  1-TOP w0.2: J16.2@2.64,54.5 R77.2@5.12,54.5
NetJ19_1: J19.1 R80.1 | length 1.9
  1-TOP w0.2: J19.1@50.6,-18.8 50.62,-18.82 R80.1@50.62,-20.7
NetJ23_5: J23.5 R93.2 | length 16.7
  1-TOP w0.2: J23.5@-29,-62.6 -29,-61.125 -19.3,-51.425 R93.2@-19.3,-49.869
NetJ24_1: J24.1 R94.1 R95.2 | length 2.6
  1-TOP w0.2: R94.1@118.4,-39.54 118.4,-38.5 J24.1@118.4,-36.925
NetJ25_1: J25.1 R94.2 R96.2 | length 6.1
  1-TOP w0.2: J25.1@118.34,-46.56 118.34,-41.5 118.34,-40.56 R94.2@118.4,-40.5
NetJ26_D1: J26.D1 R98.2 | length 10.5
  1-TOP w0.2: R98.2@-81.6,-53.68 -81.6,-56.224 J26.D1@-75.96,-61.864
NetJ26_D3: J26.D3 R97.2 | length 24.3
  1-TOP w0.2: R97.2@-82.6,-53.68 -82.6,-57.8 -77.2,-63.2 -70,-63.2 -68.664,-61.864 J26.D3@-65.21,-61.864
NetJ27_D1: J27.D1 R108.2 | length 11.3
  1-TOP w0.2: R108.2@-58.1,-52.18 -58.1,-52.8 -58.3,-53 -58.3,-58.054 J27.D1@-54.49,-61.864
NetJ27_D3: J27.D3 R107.2 | length 25.2
  1-TOP w0.2: R107.2@-59.2,-52.18 -59.2,-52.7 -58.9,-53 -58.9,-60.2 -55.8,-63.3 -48.7,-63.3 -47.264,-61.864 J27.D3@-43.74,-61.864
NetJ29_1: J29.1 J29.2 R219.1 | length 3.3
  1-TOP w0.2: J29.1@16.35,-62.736 16.35,-62.05 16.6,-61.8 16.85,-62.05 J29.2@16.85,-62.736 ; R219.1@16.58,-60.6 R219.1@16.6,-60.62
  1-TOP w0.5: 16.6,-61.8 R219.1@16.6,-60.62
NetJ29_23: J29.23 R223.1 | length 1.4
  1-TOP w0.15: R223.1@27.2,-61.4 27.2,-61.8 27.35,-61.95 J29.23@27.35,-62.736
NetJ29_24: J29.24 R222.1 | length 1.4
  1-TOP w0.15: J29.24@27.85,-62.736 27.85,-61.43 R222.1@27.9,-61.38
NetJ29_26: J29.26 R221.1 | length 1.4
  1-TOP w0.15: R221.1@28.7,-61.38 28.85,-61.53 J29.26@28.85,-62.736
NetJ29_27: J29.27 R220.1 | length 1.5
  1-TOP w0.15: J29.27@29.35,-62.736 29.35,-61.73 R220.1@29.7,-61.38
NetJ29_37: J29.37 R213.1 | length 1.4
  1-TOP w0.2: J29.37@34.35,-62.85 34.35,-61.53 R213.1@34.4,-61.48
NetJ29_39: J29.39 R212.1 | length 1.3
  1-TOP w0.2: J29.39@35.35,-62.736 35.35,-61.53 R212.1@35.4,-61.48
NetJ31_20: J31.20 L17.2 | length 2.3
  1-TOP w0.2: L17.2@9.175,-59.675 L17.2@9.7,-59.15
  1-TOP w0.5: J31.20@9.175,-61.2 L17.2@9.175,-59.675
NetJ33_A4: J33.A4 L25.2 | length 4.9
  1-TOP w0.3: J33.A4@109.43,-51.77 109.43,-50.07 111.2,-48.3 L25.2@111.2,-47.584
NetJ33_B4: J33.B4 L24.2 | length 8.2
  1-TOP w0.3: L24.2@109.3,-47.201 109.3,-49.3 108.2,-50.4 108.2,-53.16 J33.B4@109.43,-54.39
NetJ35_2: J35.2 R167.2 | length 13.2
  1-TOP w0.2: R167.2@-70.3,42.98 -70.3,47.9 -66,52.2 J35.2@-66,54.4
NetJ35_3: J35.3 R166.2 | length 7.2
  1-TOP w0.2: R166.2@-69.2,42.98 -69.2,44.2 -66,47.4 J35.3@-66,48.9
NetJ36_2: J36.2 R169.2 | length 15.1
  1-TOP w0.2: R169.2@-60.2,42.08 -60.2,43 -55.4,47.8 -55.4,50.9 -57.3,52.8 J36.2@-57.3,54.4
NetJ36_3: J36.3 R168.2 | length 8.5
  1-TOP w0.2: R168.2@-61.4,42.08 -61.4,43.7 -57.3,47.8 J36.3@-57.3,48.9
NetJ37_4: J37.4 R194.2 | length 2.4
  1-TOP w0.2: R194.2@115.2,20.58 115.2,22.4 J37.4@115.6,22.8
NetJ37_6: J37.6 R196.2 | length 2.2
  1-TOP w0.2: R196.2@111.3,20.58 J37.6@111.3,22.8
NetJ38_7: J38.7 R197.1 | length 2.4
  1-TOP w0.5: J38.7@109.3,3.7 R197.1@109.3,6.12
NetJ38_10: J38.10 R200.1 | length 2.5
  1-TOP w0.2: J38.10@103.3,0.85 103.32,0.83 R200.1@103.32,-1.6
NetJ49_2: J49.2 R236.2 | length 2.5
  1-TOP w0.2: J49.2@13.54,54.5 R236.2@16.02,54.5
NetL1_1: L1.1 R23.2 U6.2 U6.13 | length 7.1
  1-TOP w0.3: R23.2@78.7,36.5 78.7,35.6 79.1,35.2 82.95,35.2 L1.1@84.2,36.45
NetL42_2: L42.2 U29.4 | length 2.9
  1-TOP w0.2: L42.2@34.7,-55.1 35.7,-55.1 36.25,-55.65 U29.4@36.25,-56.765
NetQ1_D: Q1.D R7.1 U2.G | length 3.7
  1-TOP w0.2: R7.1@96.82,50.8 96.75,50.73 U2.G@96.75,49.55 Q1.D@99.2,49.55
NetQ6_D: Q6.D R151.1 U26.19 | length 9.6
  1-TOP w0.2: R151.1@97.3,35.52 97.3,34.7 97.9,34.1 99.8,34.1 100.525,34.825 U26.19@100.525,36.2 100.525,38.275 100.05,38.75 Q6.D@100.05,39.6
NetQ11_D: Q11.D R26.1 | length 2.5
  1-TOP w0.2: Q11.D@73.8,40 R26.1@76.32,40
NetQ12_D: Q12.D R201.1 | length 2.8
  1-TOP w0.2: R201.1@78.6,-52.92 Q12.D@78.6,-50.09
NetR3_1: R3.1 R6.1 | length 1.1
  1-TOP w0.2: R6.1@49.1,43.98 R3.1@50.2,43.98
NetR8_1: R8.1 U2.S | length 2.1
  1-TOP w0.2: R8.1@93.604,48.5 94.6,48.5 94.85,48.75 U2.S@94.85,49.55
NetR9_1: R9.1 U1.7 U2.D | length 5.8
  1-TOP w0.2: R9.1@93.98,44.4 R9.1@94,44.42 ; U1.7@95.4,44.2 94.8,44.2 94.6,44.4 94.02,44.4 R9.1@94,44.42 ; U2.D@95.8,47.25 94.55,47.25 94,46.7 R9.1@94,44.42
NetR10_1: R10.1 U1.4 | length 2.9
  1-TOP w0.2: U1.4@98.28,44.2 98.9,44.2 100,45.3 R10.1@100.682,45.3
NetR11_1: R11.1 SW3.7 | length 2.2
  1-TOP w0.2: SW3.7@118.6,35.57 120.79,35.57 R11.1@120.82,35.6
NetR19_1: R19.1 R21.2 U3.4 | length 3.5
  1-TOP w0.3: R21.2@89.3,55.4 R19.1@89.3,53.8 89.45,53.95 U3.4@91.12,53.95
NetR20_1: R20.1 R22.1 U4.3 | length 2.9
  1-TOP w0.2: U4.3@88.55,50.35 89.55,50.35 90.015,49.885 R22.1@90.3,49.885 R20.1@90.3,50.82
NetR25_1: R25.1 R26.2 U6.9 | length 4.9
  1-TOP w0.2: R25.1@77.28,39.1 77.3,39.12 77.3,40.1 U6.9@81.2,40.1
NetR27_1: R27.1 R31.2 U6.4 | length 4
  1-TOP w0.2: U6.4@82.8,40.6 83.3,40.6 84.1,41.4 R31.2@84.1,42.72 R27.1@85.1,42.72
NetR28_1: R28.1 R32.2 U6.7 | length 3.5
  1-TOP w0.2: R32.2@80.2,43.8 80.2,41.5 80.6,41.1 U6.7@81.2,41.1
NetR30_2: R30.2 U6.5 | length 1.6
  1-TOP w0.2: U6.5@83,41.1 R30.2@83,42.72
NetR36_2: R36.2 U7.AJ10 | length 31.2
  1-TOP w0.3: U7.AJ10@15.24,-6.35 v1(15.875,-6.985) ; v1(43.9,-4.8) 44.78,-4.8 R36.2@44.8,-4.78
  3-INTOP w0.3: v1(15.875,-6.985) 16.49,-7.6 41.1,-7.6 v1(43.9,-4.8)
NetR37_2: R37.2 U7.AH7 | length 28.9
  1-TOP w0.2: U7.AH7@13.97,-10.16 v1(14.605,-10.795)
  1-TOP w0.3: R37.2@14.8,-37.24 14.9,-37.14 v1(14.9,-36.4)
  6-INBOT w0.3: v1(14.605,-10.795) 15.2,-11.39 15.2,-18.5 16.5,-19.8 16.5,-23.7 14.9,-25.3 v1@14.9,-36.492
NetR38_2: R38.2 U7.F20 | length 49.9
  1-TOP w0.2: v1(-14.605,6.985) U7.F20@-13.97,6.35
  1-TOP w0.3: v1(-11,-37.4) R38.2@-9.9,-37.4
  6-INBOT w0.3: v1(-15.8,-22.5) -15.8,-32.6 v1(-11,-37.4)
  8-BOTTOM w0.3: v1(-15.8,-22.5) -16.5,-21.8 -16.5,-21.6 -16.5,4.8 -16.2,5.1 -15.5,5.1 -15.2,5.4 -15.2,6.39 v1(-14.605,6.985)
NetR39_2: R39.2 R40.2 U7.N1 | length 19.6
  1-TOP w0.4: R39.2@-6,-36.42 R40.2@-5,-36.42 ; R40.2@-5.08,-36.42 U7.N1@-5.08,-17.78
NetR41_2: R41.2 U7.E14 | length 30.2
  1-TOP w0.2: R41.2@-44.5,-1.06 -44.46,-1.1 v1(-43.7,-1.1) ; v1(-15.875,-0.635) U7.E14@-15.24,-1.27
  3-INTOP w0.2: v1(-43.7,-1.1) -30.7,-1.1 -29.7,-0.1 -17.68,-0.1 -17.145,-0.635 v1(-15.875,-0.635)
NetR42_2: R42.2 U7.AG17 | length 36
  1-TOP w0.3: U7.AG17@12.7,2.54 v1(13.335,3.175) ; v1(44.5,9.1) R42.2@44.5,9.94
  3-INTOP w0.3: v1(13.335,3.175) 14.9,4.74 14.9,5.9 15.3,6.3 41.7,6.3 v1(44.5,9.1)
NetR45_2: R45.2 U7.E5 | length 26.1
  1-TOP w0.2: v1(-15.875,-13.335) U7.E5@-15.24,-12.7
  1-TOP w0.3: v1(-14.2,-36.5) -14.2,-37.28 R45.2@-14.18,-37.3
  6-INBOT w0.3: v1(-15.875,-13.335) -16.5,-13.96 -16.5,-34.2 v1(-14.2,-36.5)
NetR52_1: R52.1 U7.D12 | length 29.3
  1-TOP w0.2: R52.1@-44.32,-7.4 v1(-43.6,-7.4) ; v1(-17.145,-4.445) U7.D12@-16.51,-3.81
  3-INTOP w0.2: v1(-43.6,-7.4) -29.85,-7.4 -27.45,-5 -17.7,-5 v1(-17.145,-4.445)
NetR53_1: R53.1 U7.D11 | length 29.4
  1-TOP w0.2: R53.1@-44.32,-8.4 v1(-43.6,-8.4) ; v1(-17.145,-5.715) U7.D11@-16.51,-5.08
  3-INTOP w0.2: v1(-43.6,-8.4) -29.125,-8.4 -26.225,-5.5 -17.36,-5.5 v1(-17.145,-5.715)
NetR54_1: R54.1 U7.D9 | length 29
  1-TOP w0.2: R54.1@-44.32,-9.4 v1(-43.6,-9.4) ; v1(-17.145,-8.255) U7.D9@-16.51,-7.62
  3-INTOP w0.2: v1(-43.6,-9.4) -43.1,-9.9 -21.95,-9.9 -20.305,-8.255 v1(-17.145,-8.255)
NetR55_1: R55.1 U7.D8 | length 30.5
  1-TOP w0.2: R55.1@-44.32,-10.4 v1(-43.6,-10.4) ; v1(-17.145,-9.525) U7.D8@-16.51,-8.89
  3-INTOP w0.2: v1(-43.6,-10.4) -24,-10.4 -22.2,-12.2 -18.8,-12.2 -17.145,-10.545 v1(-17.145,-9.525)
NetR56_1: R56.1 U7.D6 | length 28.9
  1-TOP w0.2: R56.1@-44.32,-11.4 v1(-43.6,-11.4) ; v1(-17.145,-12.065) U7.D6@-16.51,-11.43
  3-INTOP w0.2: v1(-43.6,-11.4) -24.7,-11.4 -23.4,-12.7 -17.78,-12.7 v1(-17.145,-12.065)
NetR57_1: R57.1 U7.D5 | length 29.3
  1-TOP w0.2: R57.1@-44.32,-12.4 v1(-43.6,-12.4) ; v1(-17.145,-13.335) U7.D5@-16.51,-12.7
  3-INTOP w0.2: v1(-43.6,-12.4) -43.2,-12 -41.4,-12 -41,-12.4 -25,-12.4 -23.5,-13.9 -17.71,-13.9 v1(-17.145,-13.335)
NetR61_1: R61.1 U7.E13 | length 29.9
  1-TOP w0.2: R61.1@-44.32,-3.4 v1(-43.6,-3.4) ; v1(-15.875,-3.175) U7.E13@-15.24,-2.54
  3-INTOP w0.2: v1(-43.6,-3.4) -29.4,-3.4 -28.6,-2.6 -17.8,-2.6 -17.225,-3.175 v1(-15.875,-3.175)
NetR62_1: R62.1 U7.E12 | length 29.9
  1-TOP w0.2: R62.1@-44.32,-4.4 v1(-43.6,-4.4) ; v1(-15.875,-4.445) U7.E12@-15.24,-3.81
  3-INTOP w0.2: v1(-43.6,-4.4) -28.95,-4.4 -28.35,-3.8 -16.52,-3.8 v1(-15.875,-4.445)
NetR63_1: R63.1 U7.F12 | length 37.3
  1-TOP w0.2: R63.1@-44.32,-5.4 v1(-43.6,-5.4) ; v1(-14.605,-4.445) U7.F12@-13.97,-3.81
  3-INTOP w0.2: v1(-43.6,-5.4) -44.2,-5.4 -44.4,-5.2 -44.4,-3.2 -43.9,-2.7 -30.475,-2.7 -28.975,-1.2 -16.5,-1.2 -15.2,-2.5 -15.2,-3.85 v1(-14.605,-4.445)
NetR64_1: R64.1 U7.F11 | length 36.1
  1-TOP w0.2: R64.1@-44.32,-6.4 v1(-43.6,-6.4) ; v1(-14.605,-5.715) U7.F11@-13.97,-5.08
  3-INTOP w0.2: v1(-43.6,-6.4) -44.1,-6.4 -44.5,-6.8 -44.5,-8.4 -44.05,-8.85 -42.55,-8.85 -42.3,-9.1 -28.3,-9.1 -25.3,-6.1 -17.8,-6.1 -17.5,-6.4 -15.29,-6.4 v1(-14.605,-5.715)
NetR65_1: R65.1 U8.5 | length 1.5
  1-TOP w0.2: U8.5@8.495,48.17 8.545,48.22 R65.1@10,48.22
NetR68_2: R68.2 U9.23 | length 12.7
  1-TOP w0.2: R68.2@-45.92,56.1 -45.92,58.38 -45.6,58.7 -42.1,58.7 -41.3,57.9 -41.3,53.7 -41.75,53.25 U9.23@-41.75,52.75
NetR69_2: R69.2 U9.1 | length 4.5
  1-TOP w0.2: R69.2@-45.92,54.9 -45.92,54.32 -43.7,52.1 U9.1@-42.9,52.1
NetR72_1: R72.1 U9.9 | length 1.3
  1-TOP w0.2: R72.1@-41.25,47.68 U9.9@-41.25,48.95
NetR75_1: R75.1 U10.5 | length 1.5
  1-TOP w0.2: U10.5@16.41,48.14 16.49,48.22 R75.1@17.9,48.22
NetR76_1: R76.1 R79.2 U11.4 | length 3.4
  1-TOP w0.2: R79.2@-42.6,45.2 -42.7,45.1 R76.1@-42.7,43.8 -42.45,44.05 U11.4@-40.88,44.05
NetR82_1: R82.1 R83.2 U12.4 | length 3.8
  1-TOP w0.3: R83.2@60.27,-6.2 60.18,-6.11 U12.4@60.18,-4.75 61.45,-4.75 61.8,-4.4 R82.1@61.8,-3.88
NetR84_1: R84.1 R87.1 R90.2 R91.1 R92.2 | length 13.5
  1-TOP w0.3: v2(-27.1,-50.9) R90.2@-27.1,-50.08 ; v2(-25.8,-50.9) R91.1@-25.8,-50.08 ; v2(-24.5,-50.9) R92.2@-24.5,-50.08
  1-TOP w0.5: v2(-18.6,-51.7) -18.6,-52.68 R87.1@-18.58,-52.7 R84.1@-18.58,-53.9
  8-BOTTOM w0.5: v2(-27.1,-50.9) v2(-25.8,-50.9) v2(-24.5,-50.9) -19.4,-50.9 v2(-18.6,-51.7)
NetR101_2: R101.2 R102.2 U13.15 | length 4.4
  1-TOP w0.2: R102.2@-75.7,-38.3 R101.2@-75.7,-39.8 -75.6,-39.9 -73.6,-39.9 -73.4,-39.7 U13.15@-73.4,-39.2
NetR104_2: R104.2 R113.2 U7.G2 | length 25.7
  1-TOP w0.2: R113.2@-23.5,-37.22 R104.2@-22.6,-37.22 ; R104.2@-22.5,-37.22 -22.5,-36.6 -13.335,-27.435 -13.335,-17.145 U7.G2@-12.7,-16.51
NetR106_2: R106.2 U13.30 | length 2.7
  1-TOP w0.2: U13.30@-66.15,-37.95 -65.65,-37.95 -65.5,-38.1 R106.2@-65.5,-40.12
NetR110_2: R110.2 R111.2 U14.15 | length 4.7
  1-TOP w0.2: R111.2@-56.9,-38.4 R110.2@-56.9,-40 -54.7,-40 -54.45,-39.75 U14.15@-54.45,-39.2
NetR114_2: R114.2 U14.30 | length 2.7
  1-TOP w0.2: U14.30@-47.2,-37.95 -46.55,-37.95 -46.4,-38.1 R114.2@-46.4,-39.92
NetR121_2: R121.2 U17.14 | length 1.7
  1-TOP w0.2: R121.2@44.805,-37.52 44.805,-37.1 45.005,-36.9 U17.14@45.995,-36.9
NetR124_1: R124.1 U17.13 | length 3.1
  1-TOP w0.2: R124.1@43.705,-37.52 43.705,-36.9 44.105,-36.5 U17.13@45.995,-36.5
NetR125_2: R125.2 U17.55 | length 2.4
  1-TOP w0.2: R125.2@49.505,-29.28 50.085,-29.28 50.3,-29.495 U17.55@50.3,-30.995
NetR144_1: R144.1 U20.28 | length 1.9
  1-TOP w0.2: R144.1@103.4,-35.1 103.8,-35.1 104.3,-35.6 U20.28@105.1,-35.6
NetR145_2: R145.2 U20.35 | length 2.8
  1-TOP w0.2: R145.2@103.1,-40.2 103.8,-40.2 104.1,-39.9 104.1,-39.3 104.3,-39.1 U20.35@105.1,-39.1
NetR146_2: R146.2 U20.22 | length 2.6
  1-TOP w0.2: U20.22@108.4,-34.8 108.4,-34.1 108.8,-33.7 109.3,-33.7 109.6,-33.4 R146.2@109.6,-32.98
NetR147_2: R147.2 U20.24 | length 1.9
  1-TOP w0.2: U20.24@107.4,-34.8 107.4,-33.6 107.6,-33.4 R147.2@107.6,-32.98
NetR148_2: R148.2 U20.25 | length 1.9
  1-TOP w0.2: R148.2@106.6,-32.98 106.6,-33.6 106.9,-33.9 U20.25@106.9,-34.8
NetR150_2: R150.2 R199.2 U32.A3 | length 2.5
  1-TOP w0.2: R150.2@80.78,-54.9 R199.2@80.78,-53.9 80.83,-53.85 U32.A3@82.25,-53.85
NetR153_1: R153.1 SW3.8 | length 2.2
  1-TOP w0.2: SW3.8@118.6,38.11 120.79,38.11 R153.1@120.8,38.1
NetR155_1: R155.1 SW3.6 | length 2.2
  1-TOP w0.2: SW3.6@118.6,33.03 120.73,33.03 R155.1@120.8,33.1
NetR156_1: R156.1 SW3.5 | length 2.2
  1-TOP w0.2: SW3.5@118.6,30.49 118.61,30.5 R156.1@120.82,30.5
NetR160_2: R160.2 U27.56 | length 3.7
  1-TOP w0.2: R160.2@-68.6,26.78 -68.6,27.4 -67.03,28.97 U27.56@-67.03,29.8
NetR161_2: R161.2 U27.2 | length 2.5
  1-TOP w0.2: R161.2@-66.5,26.78 -66.5,27.6 -65.8,28.3 U27.2@-65.8,28.97
NetR162_2: R162.2 U27.4 | length 2.4
  1-TOP w0.2: R162.2@-65.5,26.78 -65.5,27.2 -65,27.7 U27.4@-65,28.97
NetR163_2: R163.2 U27.54 | length 3.7
  1-TOP w0.2: R163.2@-70.22,29.3 -69.2,29.3 -67.9,30.6 U27.54@-67.03,30.6
NetR164_2: R164.2 U27.1 | length 2.9
  1-TOP w0.2: R164.2@-67.5,26.78 -67.5,27.5 -66.8,28.2 -66.5,28.2 -66.2,28.5 U27.1@-66.2,28.97
NetR193_2: R193.2 U23.5 | length 2.3
  1-TOP w0.2: R193.2@81.02,-44.6 81.02,-45.12 81.9,-46 U23.5@81.9,-46.55
NetR199_1: R199.1 R201.2 | length 1.2
  1-TOP w0.2: R201.2@78.6,-53.88 78.62,-53.9 R199.1@79.82,-53.9
NetR208_2: R208.2 SW4.3 SW4.4 | length 9
  1-TOP w0.2: R208.2@62.2,43.14 63.56,43.14 64.1,42.6 SW4.3@64.1,41.5 SW4.4@69.9,41.5
NetR209_2: R209.2 SW5.3 SW5.4 | length 9.1
  1-TOP w0.2: R209.2@51.5,43.02 53.08,43.02 53.581,42.519 SW5.3@53.581,41.5 SW5.4@59.381,41.5
NetR210_2: R210.2 U33.6 | length 1.1
  1-TOP w0.2: R210.2@62.373,-45.093 62.393,-45.073 U33.6@62.393,-43.993
NetR211_2: R211.2 U34.6 | length 1.2
  1-TOP w0.2: R211.2@60.68,35.8 60.7,35.82 60.7,36.3 60.949,36.549 U34.6@60.95,36.9 U34.6@60.95,36.9
NetR215_2: R215.2 U29.8 | length 1
  1-TOP w0.2: U29.8@37.75,-58.635 37.75,-59.47 R215.2@37.9,-59.62
NetR224_1: R224.1 R225.1 R228.2 U30.2 | length 4.5
  1-TOP w0.4: R228.2@80.38,18 R225.1@80.38,19.1 ; R224.1@80.38,20.2 R225.1@80.38,19.1 ; U30.2@82.7,19.1 R225.1@80.38,19.1
NetR229_2: R229.2 U30.8 | length 2
  1-TOP w0.2: U30.8@83.9,20 84.8,20 85,20.2 R229.2@85.82,20.2
NetR232_1: R232.1 R233.2 U31.1 | length 3.4
  1-TOP w0.2: U31.1@20.966,43.289 20.9,43.223 R232.1@20.9,41.18 R233.2@22.2,41.18
NetR234_2: R234.2 U31.2 U31.3 | length 3.4
  1-TOP w0.2: U31.2@22.236,43.289 23.506,43.289 23.506,41.186 R234.2@23.5,41.18
NetR235_2: R235.2 U31.4 | length 2.1
  1-TOP w0.2: U31.4@24.776,43.289 24.776,41.204 R235.2@24.8,41.18
NetR237_2: R237.2 U35.6 | length 1.1
  1-TOP w0.2: R237.2@82.08,-11 82.229,-10.851 82.229,-10.571 82.35,-10.45 U35.6@82.35,-10
NetR238_2: R238.2 U36.6 | length 1.9
  1-TOP w0.2: R238.2@-82.92,-51.1 -82.4,-51.1 -82.05,-50.75 U36.6@-82.05,-49.9
NetR239_2: R239.2 U37.6 | length 1.2
  1-TOP w0.2: R239.2@-59.32,-49.5 -59.32,-49.475 -59.135,-49.29 -59.11,-49.29 -58.85,-49.03 U37.6@-58.85,-48.5
NetR240_2: R240.2 R241.2 U7.L1 | length 30.2
  1-TOP w0.2: R240.2@-16.7,-37.226 -15.506,-37.226 R241.2@-15.5,-37.22 -15.5,-36 -7.62,-28.12 -7.62,-22.678 -7.62,-22.578 -7.737,-22.461 -8.036,-22.461 -8.116,-22.381 -8.116,-22.141 -8.036,-22.061 -7.182,-22.061 -7.102,-21.981 -7.102,-21.741 -7.182,-21.661 -8.036,-21.661 -8.116,-21.581 -8.116,-21.341 -8.036,-21.261 -7.182,-21.261 -7.102,-21.181 -7.102,-20.941 -7.182,-20.861 -8.036,-20.861 -8.116,-20.781 -8.116,-20.541 -8.036,-20.461 -7.182,-20.461 -7.102,-20.381 -7.102,-20.141 -7.182,-20.061 -8.02,-20.061 -8.1,-19.981 -8.1,-19.741 -8.02,-19.661 -7.737,-19.661 -7.62,-19.544 -7.62,-18.689 U7.L1@-7.62,-17.78
NetTP1_1: TP1.1 U7.AJ11 | length 32.6
  1-TOP w0.2: U7.AJ11@15.24,-5.08 v1(15.875,-5.715) ; v1(43.8,0.1) TP1.1@44.8,0.1
  3-INTOP w0.15: v1(15.875,-5.715) 16.36,-6.2 35.9,-6.2 42.2,0.1 v1(43.8,0.1)
NetTP2_1: TP2.1 U7.AH6 | length 40.9
  1-TOP w0.15: v1(44.7,-8.3) 43.2,-6.8 43.2,-2.8 TP2.1@44.8,-1.2
  1-TOP w0.2: U7.AH6@13.97,-11.43 v1(14.605,-12.065)
  3-INTOP w0.15: v1(14.605,-12.065) 15.27,-11.4 41.6,-11.4 v1(44.7,-8.3)
NetTP3_1: TP3.1 U7.AH12 | length 33.5
  1-TOP w0.2: U7.AH12@13.97,-3.81 v1(14.605,-4.445) ; v1(43.8,1.4) TP3.1@44.8,1.4
  3-INTOP w0.15: v1(14.605,-4.445) 14.955,-4.445 15.6,-3.8 36.2,-3.8 41.4,1.4 v1(43.8,1.4)
NetTP4_1: TP4.1 U7.AM19 | length 26.7
  1-TOP w0.2: U7.AM19@19.05,5.08 v1(19.685,5.715) ; v1(43.8,4.1) TP4.1@44.8,4.1
  3-INTOP w0.2: v1(19.685,5.715) 20.3,5.1 26.4,5.1 27.4,4.1 v1(43.8,4.1)
NetTP5_1: TP5.1 U7.AL19 | length 28.5
  1-TOP w0.2: U7.AL19@17.78,5.08 v1(18.415,5.715) ; v1(43.8,2.7) TP5.1@44.8,2.7
  3-INTOP w0.2: v1(18.415,5.715) 19.685,4.445 26.355,4.445 28.1,2.7 v1(43.8,2.7)
NetTP6_1: TP6.1 U9.8 | length 131.8
  1-TOP w0.15: TP6.1@44.6,5.6 44.7,5.5 TP6.1@44.8,5.6
  1-TOP w0.2: v1(-42.2,47) -42.2,47.9 -41.75,48.35 U9.8@-41.75,48.95 ; v1(43.8,5.6) TP6.1@44.6,5.6
  3-INTOP w0.2: v1(-42.2,47) -41.6,47 -40.5,45.9 -39.1,44.5 37.1,44.5 39.9,47.3 v1(41.6,47.3)
  6-INBOT w0.2: v1(41.6,47.3) 41.6,7.8 v1(43.8,5.6)
NetTP7_1: TP7.1 U13.9 | length 3.5
  1-TOP w0.2: TP7.1@-77.5,-36.2 -75.9,-36.2 -75.65,-35.95 U13.9@-74.15,-35.95
NetTP10_1: TP10.1 U14.9 | length 3.9
  1-TOP w0.2: TP10.1@-58.9,-36.4 -58.8,-36.3 -57,-36.3 -56.65,-35.95 U14.9@-55.2,-35.95
NetTP18_1: TP18.1 U30.1 | length 1.5
  1-TOP w0.2: TP18.1@81.4,20.6 82,20 U30.1@82.7,20
NetTP19_1: TP19.1 U7.C6 | length 32.2
  1-TOP w0.2: TP19.1@-45.452,-22.3 -34.5,-22.3 -28.5,-16.3 -24.9,-16.3 -20.7,-12.1 -18.45,-12.1 U7.C6@-17.78,-11.43
NetTP20_1: TP20.1 U7.C10 | length 34.1
  1-TOP w0.2: TP20.1@-45.609,-20.191 TP20.1@-45.4,-20.4 -38,-20.4 v1(-25.2,-7.6) ; v1(-18.415,-6.985) U7.C10@-17.78,-6.35
  3-INTOP w0.2: v1(-25.2,-7.6) -23.5,-7.6 -22.5,-6.6 -19.8,-6.6 -19.415,-6.985 v1(-18.415,-6.985)
NX5P3290_EN: U23.16 U32.B4 | length 10.5
  1-TOP w0.2: v1(82.5,-52.5) 82.75,-52.75 U32.B4@82.75,-53.35 ; U23.16@83.95,-47.4 84.7,-47.4 84.9,-47.2 v1(84.9,-46.9)
  8-BOTTOM w0.2: v1(82.5,-52.5) 83.1,-53.1 83.9,-53.1 84.2,-52.8 84.2,-49 84.9,-48.3 v1(84.9,-46.9)
NX5P3290_FRS: U23.1 U32.C4 | length 9.4
  1-TOP w0.2: U32.C4@83.25,-53.35 83.25,-52.85 83.4,-52.7 v1(83.4,-52.3) ; U23.1@83.5,-46.55 v1(83.5,-45.6)
  8-BOTTOM w0.2: v1(83.4,-52.3) 82.7,-51.6 82.7,-49.7 83.5,-48.9 v1(83.5,-45.6)
PCIE_1V5: J19.6 J19.28 J19.48 R81.2 R243.2 | length 27.6
  1-TOP w0.5: J19.6@52.6,-10.6 52.6,-8.9 54.2,-7.3 64.58,-7.3 R81.2@64.6,-7.28 64.62,-7.3 65.8,-7.3 70.6,-7.3 72.6,-9.3 J19.48@72.6,-10.6 ; J19.28@64.6,-10.6 R81.2@64.6,-7.5
PCIE_I2C_SCL: J19.30 R188.2 | length 32.3
  1-TOP w0.15: J19.30@65.4,-10.6 v1(65.4,-9.1)
  1-TOP w0.2: R188.2@66.2,20.18 v1(66.2,20.8)
  6-INBOT w0.15: v1(65.4,-9.1) 65.4,12.507 65.7,12.807 65.7,17.554 ; 65.7,17.6 66.2,18.1 v1(66.2,20.8)
PCIE_I2C_SDA: J19.32 R190.2 | length 27.7
  1-TOP w0.2: J19.32@66.2,-10.6 v1(66.2,-9.1) ; v1(66.2,16.5) R190.2@66.2,17.12
  6-INBOT w0.15: v1(66.2,-9.1) 66.2,12.6 v1(66.2,16.5)
PCIE_UIM_CLK: J19.12 R86.1 | length 12
  1-TOP w0.2: J19.12@55,-10.6 55,-13.4 57.6,-16 R86.1@57.6,-21.52
PCIE_UIM_DATA: J19.10 R89.1 | length 12.2
  1-TOP w0.2: J19.10@54.2,-10.6 54.2,-13.4 57,-16.2 57,-20.3 56.6,-20.7 R89.1@56.6,-21.52
PCIE_UIM_PWR: C50.2 C51.2 C52.2 C53.2 J19.8 J22.1 | length 70.5
  1-TOP w0.5: J19.8@53.4,-10.6 53.4,-9.3 54.1,-8.6 56.8,-8.6 59.4,-11.2 59.4,-27.2 73,-40.8 C50.2@73,-46.701 ; J22.1@72.78,-66.7 72.78,-62.48 71.8,-61.5 71.8,-57.6 73,-56.4 C53.2@73,-50.781 ; C53.2@72.98,-50.8 C52.2@72.98,-49.8 72.98,-48.52 C51.2@73.1,-48.4 ; C51.2@73,-48.4 C50.2@73,-47
PCIE_UIM_RST: D11.2 J19.14 J22.2 | length 63.5
  1-TOP w0.2: J19.14@55.8,-10.6 55.8,-13.4 58.2,-15.8 58.2,-27.607 70.7,-40.107 70.7,-50.3 70.45,-50.55 D11.2@70.1,-50.55 70.1,-54 69.5,-54.6 69.5,-63.8 70.24,-64.54 J22.2@70.24,-66.92
PCIE_UIM_VPP: D12.2 J19.16 J22.6 | length 56
  1-TOP w0.2: J19.16@56.6,-10.6 56.6,-13.4 58.7,-15.5 58.7,-27.4 71.9,-40.6 71.9,-50.4 71.75,-50.55 D12.2@71.3,-50.55 71.3,-53.7 70.24,-54.76 J22.6@70.24,-59.3
PCM_CLK: J44.3 R161.1 U7.G13 | length 163
  1-TOP w0.15: v1(-25.2,55.3) -25.2,59.3 -25.24,59.34 J44.3@-24.04,60.54
  1-TOP w0.2: v1(-66.5,25.18) R161.1@-66.5,25.82 ; v1(-13.335,-3.175) U7.G13@-12.7,-2.54
  3-INTOP w0.15: v1(-72.7,12.5) -45.6,12.5 -39.65,6.55 -25.283,6.55 -25.208,6.55 -25.12,6.638 -25.12,7.008 -25.05,7.078 -24.84,7.078 -24.77,7.008 -24.77,6.619 -24.7,6.549 -24.49,6.549 -24.42,6.619 -24.42,7.008 -24.35,7.078 -24.14,7.078 -24.07,7.008 -24.07,6.619 -24,6.549 -23.79,6.549 -23.72,6.619 -23.72,7.008 -23.65,7.078 -23.44,7.078 -23.37,7.008 -23.37,6.619 -23.3,6.549 -23.09,6.549 -23.02,6.619 -23.02,6.783 -22.95,6.853 -22.74,6.853 -22.67,6.783 -22.67,6.638 -22.582,6.55 -20.886,6.55 -20.6,6.55 -12.895,6.55 -12.5,6.155 -12.5,-2.34 v1(-13.335,-3.175)
  6-INBOT w0.15: v1(-72.7,12.5) -72.7,18.98 v1(-66.5,25.18) -67,25.68 -67,36.607 -68.2,37.807 -68.2,40.007 -67.407,40.8 -54.3,40.8 -46.9,48.2 -34.3,48.2 -27.2,55.3 v1(-25.2,55.3)
PCM_IN: J44.5 R164.1 U7.G14 | length 165.1
  1-TOP w0.15: v1(-22.8,55.8) -22.8,59.24 J44.5@-21.5,60.54
  1-TOP w0.2: v1(-67.5,25.18) R164.1@-67.5,25.82 ; v1(-13.335,-1.905) U7.G14@-12.7,-1.27
  3-INTOP w0.15: v1(-73.2,12) -45.7,12 -39.875,6.175 -25.632,6.175 -25.207,6.175 -25.12,6.087 -25.12,5.745 -25.05,5.675 -24.84,5.675 -24.77,5.745 -24.77,6.125 -24.7,6.195 -24.49,6.195 -24.42,6.125 -24.42,5.745 -24.35,5.675 -24.14,5.675 -24.07,5.745 -24.07,6.125 -24,6.195 -23.79,6.195 -23.72,6.125 -23.72,5.745 -23.65,5.675 -23.44,5.675 -23.37,5.745 -23.37,6.125 -23.3,6.195 -23.09,6.195 -23.02,6.125 -23.02,5.745 -22.95,5.675 -22.74,5.675 -22.67,5.745 -22.67,6.125 -22.6,6.195 -22.39,6.195 -22.32,6.125 -22.32,5.912 -22.25,5.842 -22.04,5.842 -21.97,5.912 -21.97,6.087 -21.882,6.175 -20.635,6.175 -20.575,6.175 -13.05,6.175 -12.875,6 -12.875,-1.445 v1(-13.335,-1.905)
  6-INBOT w0.15: v1(-73.2,12) -73.2,19.48 v1(-67.5,25.18) -67.5,36.4 -68.7,37.6 -68.7,40.214 -67.614,41.3 -54.5,41.3 -47.1,48.7 -39.8,48.7 -39.195,49.305 -33.795,49.305 -27.3,55.8 v1(-22.8,55.8)
PCM_MCLK: J44.1 U7.A26 | length 51.5
  1-TOP w0.2: J44.1@-26.56,60.54 -28.06,60.54 -28.3,60.3 -28.3,56.5 -21.3,49.5 v1(-21.3,38.2) ; v1(-20.955,14.605) U7.A26@-20.32,13.97
  6-INBOT w0.2: v1(-21.3,38.2) -21.3,14.95 v1(-20.955,14.605)
PCM_OUT: J44.7 R163.1 U7.F13 | length 163.3
  1-TOP w0.2: v1(-71.82,29.3) R163.1@-71.18,29.3 ; v1(-14.605,-3.175) U7.F13@-13.97,-2.54
  3-INTOP w0.15: v1(-73.7,11.5) -45.8,11.5 -39.575,5.275 -14.23,5.275 -13.775,4.82 -13.775,-2.345 v1(-14.605,-3.175)
  6-INBOT w0.15: v1(-73.7,11.5) -73.7,27.42 v1(-71.82,29.3) -70.1,31.02 -70.1,39.5 -67.8,41.8 -54.7,41.8 -47.3,49.2 -40,49.2 -39.4,49.8 -33.9,49.8 -27.4,56.3 -20.9,56.3 -20.22,56.98 -20.22,59.28 J44.7@-18.96,60.54
PCM_SYNC: J44.9 R162.1 U7.F14 | length 169.1
  1-TOP w0.2: v1(-65.5,25.18) R162.1@-65.5,25.82 ; v1(-14.605,-1.905) U7.F14@-13.97,-1.27
  3-INTOP w0.15: v1(-72.2,11) -45.9,11 -39.825,4.925 -27.397,4.925 -26.972,4.925 -26.884,4.837 -26.884,4.517 -26.814,4.447 -26.604,4.447 -26.534,4.517 -26.534,4.884 -26.464,4.954 -26.254,4.954 -26.184,4.884 -26.184,4.517 -26.114,4.447 -25.904,4.447 -25.834,4.517 -25.834,4.884 -25.764,4.954 -25.554,4.954 -25.484,4.884 -25.484,4.517 -25.414,4.447 -25.204,4.447 -25.134,4.517 -25.134,4.884 -25.064,4.954 -24.854,4.954 -24.784,4.884 -24.784,4.517 -24.714,4.447 -24.504,4.447 -24.434,4.517 -24.434,4.884 -24.364,4.954 -24.154,4.954 -24.084,4.884 -24.084,4.517 -24.014,4.447 -23.804,4.447 -23.734,4.517 -23.734,4.884 -23.664,4.954 -23.454,4.954 -23.384,4.884 -23.384,4.517 -23.314,4.447 -23.104,4.447 -23.034,4.517 -23.034,4.884 -22.964,4.954 -22.754,4.954 -22.684,4.884 -22.684,4.517 -22.614,4.447 -22.404,4.447 -22.334,4.517 -22.334,4.884 -22.264,4.954 -22.054,4.954 -21.984,4.884 -21.984,4.623 -21.914,4.553 -21.704,4.553 -21.634,4.623 -21.634,4.837 -21.546,4.925 -21.225,4.925 -14.375,4.925 -14.125,4.675 -14.125,-1.425 v1(-14.605,-1.905)
  6-INBOT w0.15: v1(-72.2,11) -72.2,18.48 v1(-65.5,25.18) -66.5,26.18 -66.5,36.814 -67.7,38.014 -67.7,39.8 -67.2,40.3 -54.1,40.3 -46.695,47.705 -34.195,47.705 -27.1,54.8 -20,54.8 -17.7,57.1 -17.7,59.26 J44.9@-16.42,60.54
POR_B: J20.10 R6.2 R152.1 U7.AH10 | length 188.7
  1-TOP w0.2: v1(-17.34,42.9) J20.10@-17.34,44.768 ; U7.AH10@13.97,-6.35 v1(14.605,-6.985) ; v1(26,39.8) 47.7,39.8 v1(49.2,41.3) R6.2@49.2,43.02
  1-TOP w0.3: R152.1@105.4,38.6 v1(106.4,38.6)
  3-INTOP w0.2: v1(-17.34,42.9) -16.64,42.2 -10.3,42.2 -9.8,41.7 1.5,41.7 3.4,39.8 v1(26,39.8) ; v1@49.15,41.35 49.1,41.3 v1(49.2,41.3) 52.1,41.3 56.7,45.9 94.8,45.9 95.6,45.1 98.7,45.1 105.2,38.6 v1(106.4,38.6)
  6-INBOT w0.2: v1(14.605,-6.985) 15.2,-6.39 15.2,4.024 14,5.224 14,15.8 26,27.8 v1(26,39.8)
